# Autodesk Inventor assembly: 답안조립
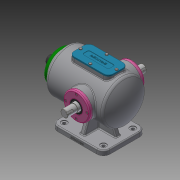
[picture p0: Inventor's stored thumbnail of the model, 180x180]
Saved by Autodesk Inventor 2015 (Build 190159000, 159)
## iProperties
Created: 2021-11
Part Number: 답안조립
Document SubType Name: Assembly
Designer: 101256544
Author: 101256544
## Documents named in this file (14)
- C:\Users\101256544\Desktop\711106V1011\답안조립.iam
- C:\Users\101256544\Desktop\711106V1011\베어링 6205.ipt
- 베어링 6205.ipt
- C:\Users\101256544\Desktop\711106V1011\본체.ipt
- C:\Users\101256544\Desktop\711106V1011\볼트 M4x0.7.ipt
- C:\Users\101256544\Desktop\711106V1011\부시.ipt
- C:\Users\101256544\Desktop\711106V1011\상부커버.ipt
- C:\Users\101256544\Desktop\711106V1011\슬라이드 커버.ipt
- C:\Users\101256544\Desktop\711106V1011\슬라이드.ipt
- C:\Users\101256544\Desktop\711106V1011\오일실.ipt
- 오일실.ipt
- C:\Users\101256544\Desktop\711106V1011\육각머리볼트 M4.ipt
- C:\Users\101256544\Desktop\711106V1011\축 커버.ipt
- C:\Users\101256544\Desktop\711106V1011\편심축.ipt
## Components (12 placed, 1 different names)
1. M4x0.7:1
2. M4x0.7:4
3. M4x0.7:5
4. M4x0.7:6
5. M4x0.7:2
6. M4x0.7:7
7. M4x0.7:8
8. M4x0.7:9
9. M4x0.7:3
10. M4x0.7:10
11. M4x0.7:11
12. M4x0.7:12
